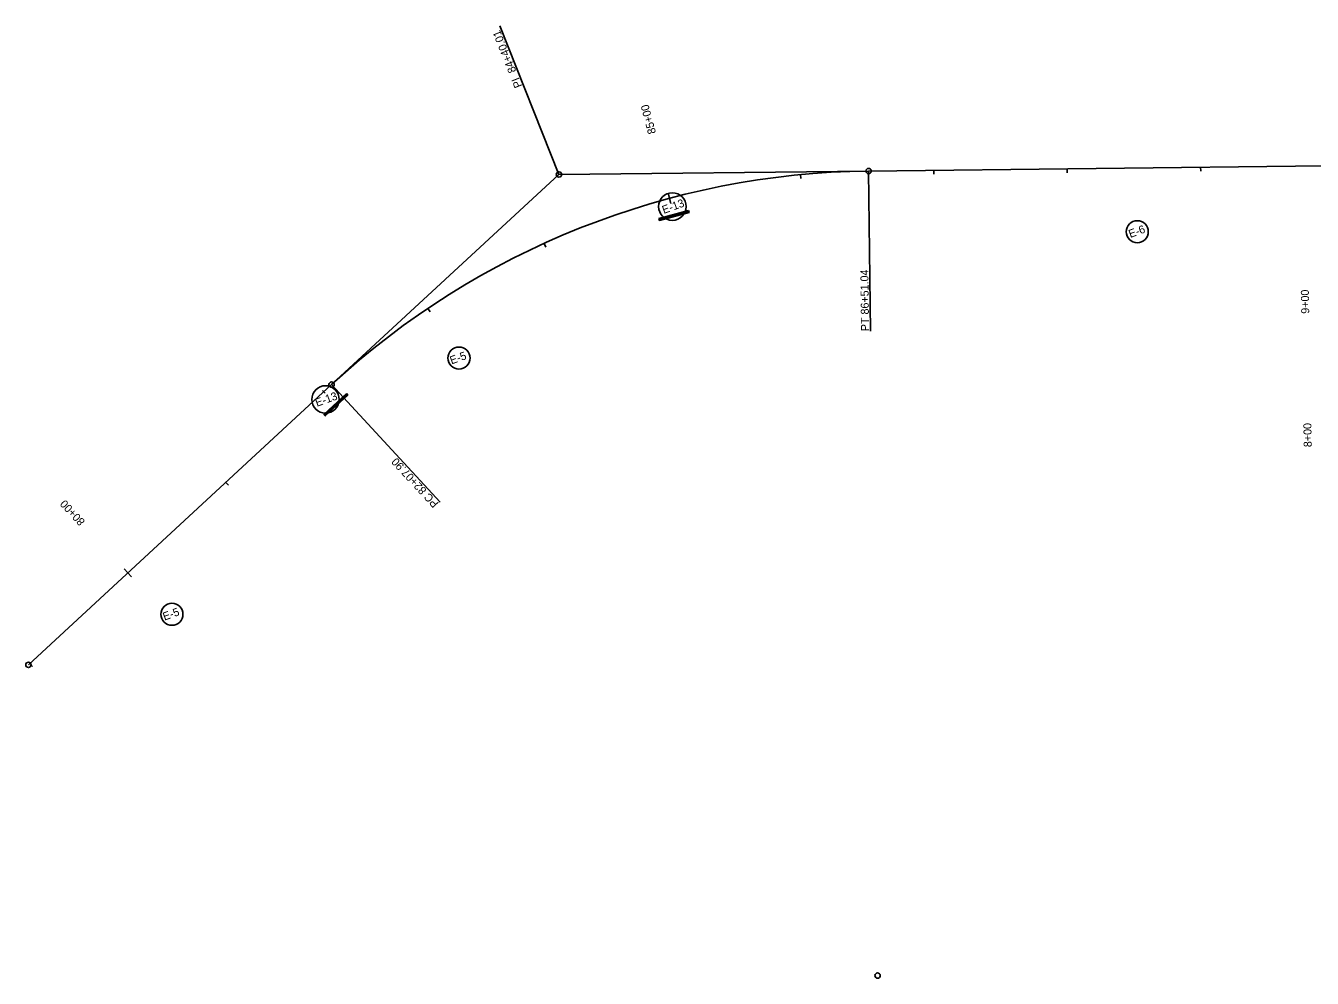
# Model space of a CAD drawing. Extents: x 1710760 to 1713003, y 548603 to 551142.
# Drawn here: x 1710760 to 1711724, y 548603 to 549317 of the extents above; entities that cross this region are included whole.
import ezdxf

# ---------------------------------------------------------------- set-up
doc = ezdxf.new("R2010")
doc.units = 0
for name, color, linetype in [('R_Erosion', 7, 'Continuous'), ('R_Erosion_STG 2', 7, 'Continuous'), ('R_Horz Alg', 7, 'Continuous'), ('R_Horz Alg Annot', 7, 'Continuous')]:
    doc.layers.add(name, color=color, linetype=linetype)

msp = doc.modelspace()

# ---------------------------------------------------------------- linework, layer by layer
at = {"layer": 'R_Erosion'}
for p, q in [((1711256.87, 549178.94), (1711234.65, 549172.99)), ((1711243.76, 549173.87), (1711244.82, 549175.71)), ((1711245.13, 549174.24), (1711246.19, 549176.08)), ((1711246.49, 549174.6), (1711247.55, 549176.44)), ((1711247.86, 549174.97), (1711248.92, 549176.81)), ((1711249.22, 549175.34), (1711250.28, 549177.17)), ((1711250.59, 549175.7), (1711251.65, 549177.54)), ((1711251.96, 549176.07), (1711253.02, 549177.9)), ((1711253.32, 549176.43), (1711254.38, 549178.27)), ((1711254.69, 549176.8), (1711255.75, 549178.64)), ((1711256.05, 549177.16), (1711256.93, 549178.69)), ((1711234.81, 549172.38), (1711235.26, 549173.15)), ((1711235.56, 549171.68), (1711236.62, 549173.51)), ((1711236.93, 549172.04), (1711237.99, 549173.88)), ((1711238.29, 549172.41), (1711239.36, 549174.25)), ((1711239.66, 549172.77), (1711240.72, 549174.61)), ((1711241.03, 549173.14), (1711242.09, 549174.98)), ((1711242.39, 549173.51), (1711243.45, 549175.34)), ((1711000.34, 549041.65), (1710983.45, 549026.04)), ((1710999.28, 549038.64), (1710999.37, 549040.75)), ((1711000.32, 549039.6), (1711000.4, 549041.59)), ((1710988.9, 549029.04), (1710988.98, 549031.16)), ((1710989.93, 549030), (1710990.02, 549032.12)), ((1710990.97, 549030.96), (1710991.06, 549033.08)), ((1710992.01, 549031.92), (1710992.1, 549034.04)), ((1710993.05, 549032.88), (1710993.13, 549035)), ((1710994.09, 549033.84), (1710994.17, 549035.96)), ((1710995.13, 549034.8), (1710995.21, 549036.92)), ((1710996.17, 549035.76), (1710996.25, 549037.88)), ((1710997.21, 549036.72), (1710997.29, 549038.84)), ((1710998.24, 549037.68), (1710998.33, 549039.8)), ((1710983.76, 549025.71), (1710983.79, 549026.36)), ((1710984.74, 549025.2), (1710984.83, 549027.32)), ((1710985.78, 549026.16), (1710985.86, 549028.28)), ((1710986.82, 549027.12), (1710986.9, 549029.24)), ((1710987.86, 549028.08), (1710987.94, 549030.2))]:
    msp.add_line(p, q, dxfattribs=at)
for points in [[(1711234.65, 549172.99), (1711235.04, 549171.54), (1711257.25, 549177.49), (1711256.87, 549178.94)], [(1710983.45, 549026.04), (1710984.47, 549024.94), (1711001.36, 549040.55), (1711000.34, 549041.65)]]:
    msp.add_lwpolyline(points, dxfattribs=at)
for centre in [(1711593.19, 549163), (1711084.74, 549068.32), (1710869.56, 548876.31)]:
    msp.add_circle(centre, 8.26, dxfattribs=at)
at = {"layer": 'R_Erosion_STG 2'}
for centre in [(1711244.68, 549181.87), (1710984.67, 549037.29)]:
    msp.add_circle(centre, 10.32, dxfattribs=at)
at = {"layer": 'R_Horz Alg'}
for p, q in [((1711391.77, 549208.53), (1711733, 549212.35)), ((1710761.95, 548838.38), (1710989.21, 549048.39))]:
    msp.add_line(p, q, dxfattribs=at)
msp.add_arc((1711398.54, 548605.45), 603.11, 90.64281, 132.74131, dxfattribs=at)
at = {"layer": 'R_Horz Alg Annot'}
for p, q in [((1710989.21, 549048.39), (1711159.68, 549205.92)), ((1711159.68, 549205.92), (1711391.77, 549208.53))]:
    msp.add_line(p, q, dxfattribs=at)
for points in [[(1711159.68, 549205.92), (1711115.32, 549317.42)], [(1711341.11, 549202.81), (1711340.82, 549205.8)], [(1711391.77, 549208.53), (1711393.12, 549088.53)], [(1711440.76, 549206.08), (1711440.73, 549209.07)], [(1711540.75, 549207.2), (1711540.72, 549210.2)], [(1711640.75, 549208.32), (1711640.71, 549211.32)], [(1711241.49, 549191.9), (1711243.56, 549184.17)], [(1711149.75, 549151.57), (1711148.51, 549154.3)], [(1711063.03, 549103.01), (1711061.35, 549105.5)], [(1710984.43, 549041.93), (1710982.39, 549044.13)], [(1710989.21, 549048.39), (1711070.66, 548960.26)], [(1710912, 548972.96), (1710909.97, 548975.16)], [(1710833.81, 548910.23), (1710839.24, 548904.35)], [(1710765.12, 548837.22), (1710763.08, 548839.42)]]:
    msp.add_lwpolyline(points, dxfattribs=at)
for centre in [(1711159.68, 549205.92), (1711391.77, 549208.53), (1710989.21, 549048.39), (1710761.95, 548838.38), (1711398.54, 548605.45)]:
    msp.add_circle(centre, 2, dxfattribs=at)

# ---------------------------------------------------------------- texts
at = {"layer": 'R_Erosion'}
for s, p in [('E-6 ', (1711587.97, 549158.33)), ('E-5 ', (1711079.17, 549063.52)), ('E-5 ', (1710863.99, 548871.5))]:
    msp.add_text(s, height=5.999, rotation=20, dxfattribs=at).set_placement(p)
at = {"layer": 'R_Erosion_STG 2'}
for p in [(1711238.27, 549176.34), (1710978.26, 549031.76)]:
    msp.add_text('E-13', height=5.999, rotation=20, dxfattribs=at).set_placement(p)
at = {"layer": 'R_Horz Alg Annot'}
for s, rotation, p in [('PI  84+40.01', 111.69206, (1711132.24, 549272.19)), ('85+00', 104.99186, (1711232.49, 549237.11)), ('PT 86+51.04', 90.64281, (1711392.12, 549088.52)), ('9+00', 91.07865, (1711722.14, 549101.6)), ('8+00', 91.07865, (1711724.02, 549001.62)), ('PC 82+07.90', 132.74131, (1711069.92, 548959.58)), ('80+00', 132.74131, (1710804.79, 548946.05))]:
    msp.add_text(s, height=6, rotation=rotation, dxfattribs=at).set_placement(p)

doc.saveas('drawing.dxf')
